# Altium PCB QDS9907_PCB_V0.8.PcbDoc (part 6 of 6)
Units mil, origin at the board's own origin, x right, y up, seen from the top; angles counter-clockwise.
Board outline 3410.03 x 4010.03 mil, 8 copper layers (Top Layer, GND1, INT1, INT2, PWR1, GND2, GND3, Bottom Layer), stack 81.668 mil thick; 250 components, 129 nets, 7010 pads, 701 vias.
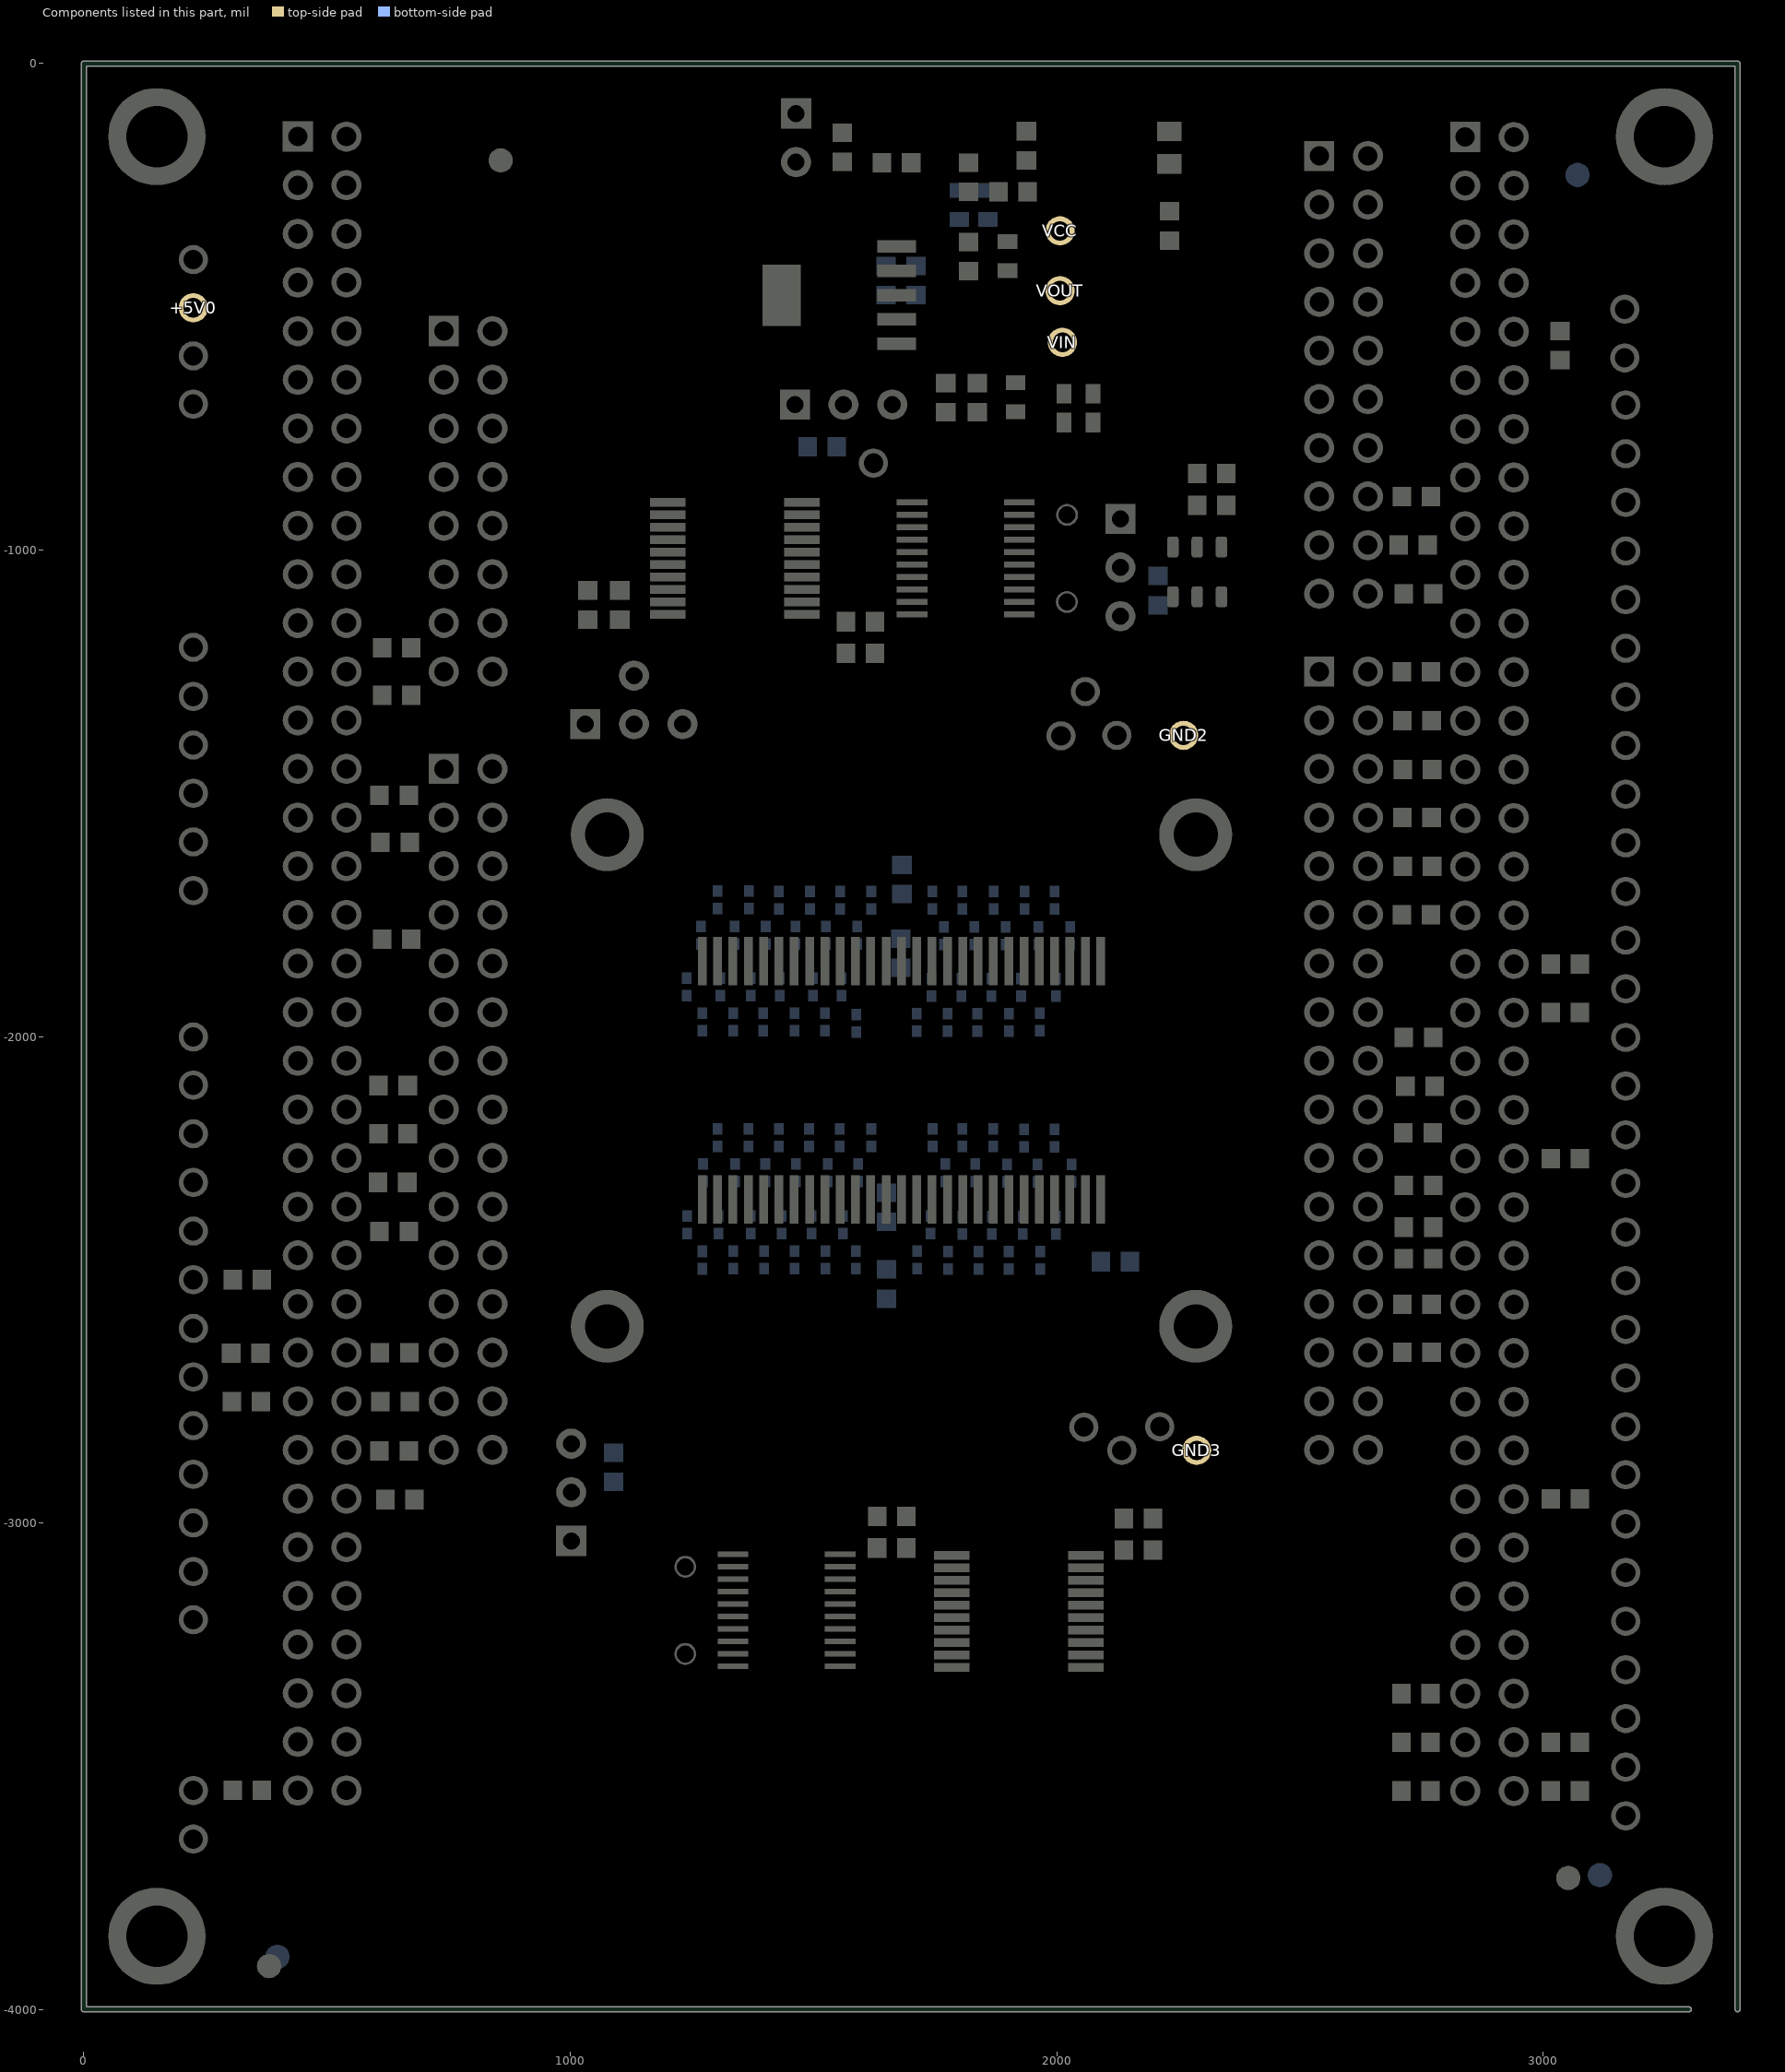
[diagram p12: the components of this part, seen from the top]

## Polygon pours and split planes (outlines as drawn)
+5V0 on PWR1 "+5V" (solid, remove dead copper, pour order 22): -8.31,-1058 1104,-1058 1247,-915 2003,-915 2003,-591.74 1748,-591.74 1748,-2 -6.17,-2
VCC on PWR1 "VCC" (solid, remove dead copper, pour order 21): 9,-1064 1112,-1064 1250,-926 2010,-926 2010,-592.67 1757,-592.67 1757,0 3404,0 3404,-3994.98 9,-3994.98
+5V0 on Top Layer "Top Layer-No Net" (solid, remove dead copper, pour order 23): 608,-798 606,-800 606,-973 636,-1003 999,-1003 1056,-946 1056,-865 1019,-828 990,-798
VOUT on Top Layer "Top Layer-No Net" (solid, remove dead copper, pour order 24): 1735,-424 1735,-411 1742,-404 1744,-402 1753,-402 2105,-402 2118,-415 2128,-425 2128,-454 2128,-481 2114,-495 2094,-515 2063,-515 1990,-515 1968,-493 1962,-487 1845,-487 1814,-487 1780,-453 1778,-451 1760,-451 1746,-451 1739,-444 1735,-440 1735,-424
GND on Top Layer "GND" (solid, remove dead copper, pour order 47): 0,-4000 0,0 3399,0 3399,-4000
VOUT on Bottom Layer "Top Layer-No Net" (solid, remove dead copper, pour order 25): 1788,-386.13 1950.13,-386.13 1954,-390 1962,-398 1965,-398 2118,-398 2131,-411 2145,-425 2145,-443 2145,-493 2128,-510 2122,-516 2077,-516 1979,-516 1961,-498 1953,-490 1935,-490 1837,-490 1788,-441 1788,-386.13
VIN on Bottom Layer "Top Layer-No Net" (solid, remove dead copper, pour order 26): 1726,-512 1944,-512 1956,-524 1970,-538 1985,-538 2049,-538 2065,-554 2072,-561 2072,-577 2072,-594 2057,-609 2042,-624 2017,-624 1756,-624 1728,-596 1718,-586 1718,-555 1718,-521 1726,-513
GND on Bottom Layer "GND" (solid, remove dead copper, pour order 45): 0,-4000 0,0 3399,0 3399,-4000
GND on GND1 "Top Layer-GND" (solid, remove dead copper, pour order 39): 0,-4002.85 0,0 3400,0 3400,-4005.02 0,-4005.01
GND on GND2 "Top Layer-GND" (solid, remove dead copper, pour order 41): 2,-3992 0,0 3400,0 3398,-3992 0,-3992
GND on GND3 "Top Layer-GND" (solid, remove dead copper, pour order 43): 3,-3999 0,-1.08 3400,0 3400,-3999 0,-3999
GND on INT1 "GND" (solid, remove dead copper, pour order 51): 0,-4000 0,0 3399,0 3399,-4000
GND on INT2 "GND" (solid, remove dead copper, pour order 49): 0,-4000 0,0 3399,0 3399,-4000

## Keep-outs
Keep-Out Layer:
  lines w25: 0,-4000 0,0 3399,0 3399,-4000 0,-4000

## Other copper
Top Layer:
  rectangle net GND: 2178,-3077 2263,-2965
  rectangle net GND: 1696,-3037 1785,-2961
  rectangle net GND: 1671.11,-3073 1720,-2961
  rectangle net GND: 1509.5,-1239.5 1566.5,-1168.5
  rectangle net GND: 1545.5,-1239.5 1587.5,-1122.5
  rectangle net +5V0: 1870,-770 1965,-698
  rectangle net +5V0: 1963,-770 2033,-645
  rectangle net NetR14_1: 1630,-390 1849,-331
  rectangle net GND: 1340.55,-636 1516,-325
  rectangle net VIN: 1742,-678 1948,-510
  rectangle net VIN: 1630,-550 1750,-510
  rectangle net VCC: 1865,-390 2103,-300
  rectangle net VOUT: 1740.99,-437 1789,-405.01
  pour cut-out: 2224,-1009 2350,-1007 2353,-1075 2220,-1075 2220,-1014
  pour cut-out: 3178,-3221 3192,-3274 3153,-3285 3158,-3227
  pour cut-out: 3199,-811 3199,-896 3177,-869 3181,-790
  pour cut-out: 3197,-1105 3195,-1599 3119,-1534 3169,-1116
  pour cut-out: 3025,-2272 3005,-2324 2984,-2293 2982,-2280
  pour cut-out: 3194,-3421 3192,-3487 3154,-3477 3157,-3423
  pour cut-out: 2680,-3451 2679,-3521.74 2720,-3521 2734,-3481
  pour cut-out: 3194,-2328.5 3200,-2377.5 3171,-2367.5 3156,-2328.5 3159,-2326.5
  pour cut-out: 3191,-3323 3192,-3387 3164,-3377 3167,-3336
  pour cut-out: 3192,-2423 3192,-2490 3173,-2479 3169,-2426
  pour cut-out: 3202,-2221 3192,-2287 3182,-2280 3171,-2231
  pour cut-out: 2613,-1243 2623,-1776 2675,-1770 2652,-1259
  pour cut-out: 2751,-866 2815,-825 2899.54,-829.1 2940,-851 2931,-923.8 2907,-934
  pour cut-out: 2619,-888 2633,-1255 2691,-1252 2673,-890
  pour cut-out: 2862.5,-996.5 2847.5,-1107.5 2772.5,-1084.5 2795.5,-1006.5 2800.5,-996.5
  pour cut-out: 2001.21,-942.91 2091.21,-894.91 2092.21,-963.91 2065.79,-1000.26 2022.21,-1007.74
  pour cut-out: 1967.5,-2964 2098.5,-2994 2011.5,-3052 1963.5,-3056 1907.5,-3036
  pour cut-out: 1811,-3275 1809,-3322 1741,-3322 1733,-3307 1745,-3289
  pour cut-out: 200,-2800 198,-2886 225,-2900 239,-2837 239,-2813
  pour cut-out: 200,-2605 199,-2778 235,-2771 239,-2634
  pour cut-out: 210,-2516 203,-2585 225,-2600 251,-2526
  pour cut-out: 453,-1683 547,-1671 550,-1632 501,-1609
  pour cut-out: 452,-1737 530,-1733 552,-1788 511,-1825 456,-1809
  pour cut-out: 703,-1635 694.34,-1755.69 906,-1747 932,-1717 861,-1630 778,-1606
  pour cut-out: 765,-1409 841.9,-1404.03 820,-1446 812,-1462
  pour cut-out: 872,-1464 882.86,-1633.28 844,-1640 823,-1549 847,-1481
  pour cut-out: 2122,-487 2191,-534 2163,-554 2096,-504
  pour cut-out: 2081,-593 2038,-667 2031.52,-613.55 2039.69,-608.48
  pour cut-out: 1867.87,-405.13 1847.18,-405.13 1845.04,-403 1848.73,-399.31 1848.73,-387.96 1859.96,-387.96 1867.87,-395.87
  pour cut-out: 1779.87,-425.13 1759.18,-425.13 1757.04,-423 1760.73,-419.31 1760.73,-407.96 1771.96,-407.96 1779.87,-415.87
  pour cut-out: 1482.16,-3270 1664,-3270 1664,-3326 1463,-3326 1463,-3268.08
  pour cut-out: 1409.15,-3192.95 1502.6,-3286.4 1463,-3326 1363.89,-3226.89 1404.2,-3186.59 1402.78,-3185.17
  pour cut-out: 1403,-3229 1535.16,-3229 1535.16,-3285 1395,-3285 1395,-3228 1393,-3228
  pour cut-out: 2036,-3228 2036,-3360.16 1980,-3360.16 1980,-3220 2037,-3220 2037,-3218
  pour cut-out: 1978.05,-3226.92 1845.89,-3226.92 1845.89,-3170.92 1986.05,-3170.92 1986.05,-3227.92 1988.05,-3227.92
  pour cut-out: 1690,-3346 1690,-3213.84 1746,-3213.84 1746,-3354 1689,-3354 1689,-3356
  pour cut-out: 1608.84,-3073 1741,-3073 1741,-3129 1600.84,-3129 1600.84,-3072 1598.84,-3072
  pour cut-out: 2170,-1107.08 2170,-974.92 2226,-974.92 2226,-1115.08 2169,-1115.08 2169,-1117.08
  pour cut-out: 1512.5,-918.5 1512.5,-877.5 1531.5,-877.5 1531.5,-926.5 1508.5,-926.5 1508.5,-918.5
  pour cut-out: 1451.5,-880.18 1451.5,-948.5 1320.5,-948.5 1320.5,-873.5
  pour cut-out: 183.34,-1590 257,-1590 257,-1511 183.34,-1511
  pour cut-out: 2827,-2000 2827,-2095 2827,-1813 2960,-1813 2960,-2082 2826,-2082 2826,-2084
  pour cut-out: 1982.87,-522.13 1962.18,-522.13 1960.04,-520 1963.73,-516.31 1963.73,-504.96 1974.96,-504.96 1982.87,-512.87
  pour cut-out: 1787.72,-474.99 1787.72,-501.72 1795,-509 1806.91,-497.09 1814,-497.09 1814,-490.6 1796,-472.6 1793.61,-474.99
  pour cut-out: 2739,-2032 2739,-1972.23 2738.77,-1972 2749,-1972 2749,-2032
  pour cut-out: 646,-2721 646,-2780.77 646.23,-2781 636,-2781 636,-2721
  pour cut-out: 631,-2134.89 631,-2075.12 630.77,-2074.89 641,-2074.89 641,-2134.89
  pour cut-out: 645,-2620 645,-2679.77 645.23,-2680 635,-2680 635,-2620
  pour cut-out: 634,-2882 634,-2822.23 633.77,-2822 644,-2822 644,-2882
  pour cut-out: 633,-1534 633,-1474.23 632.77,-1474 643,-1474 643,-1534
  pour cut-out: 639,-1831 639,-1771.23 638.77,-1771 649,-1771 649,-1831
  pour cut-out: 1621.74,-448.93 1618,-445.19 1618,-328.74 1625.82,-320.91 1731.96,-320.91 1737,-325.96 1729.66,-333.3 1729.66,-448.93
  pour cut-out: 1844,-179 1844,-239 1855,-239 1855,-249 1794,-249 1794,-229 1616,-229 1616,-179
  pour cut-out: 1794,-249 1794,-331 1965,-331 1965,-178 1915,-178 1915,-239 1855,-239 1855,-249
  pour cut-out: 2207,-329 2257,-329 2257,-339 2207,-339
  pour cut-out: 1985,-698 1861,-698 1861,-675 1965,-675 1965,-685 1970,-685
  pour cut-out: 640,-1329 640,-1269.23 639.77,-1269 650,-1269 650,-1329
  pour cut-out: 341,-2471 341,-2530.77 341.23,-2531 331,-2531 331,-2471
  pour cut-out: 2744,-3581 2744,-3521.23 2744.23,-3521 2734,-3521 2734,-3581
  pour cut-out: 2744,-3481 2744,-3421.23 2744.23,-3421 2734,-3421 2734,-3481
  region net VCC: 1237.5,-1123.5 1147.81,-1123.5 1016.5,-1123.5 1016.5,-1187.5 1237.5,-1187.5
  region net VCC: 1737.5,-1126 1657,-1126 1607.5,-1126 1607.5,-1240.5 1693.5,-1240.5 1737.5,-1196.5
  region net VCC: 2023,-3076 2112.69,-3076 2163,-3076 2163,-2970 2068,-2970 2023,-3015
  region net VCC: 1523,-3072 1602,-3072 1651,-3072 1651,-2966 1560,-2966 1523,-3003
  pour cut-out: 2728,-1780 2728,-1720.23 2727.77,-1720 2738,-1720 2738,-1780
  pour cut-out: 2728,-1680 2728,-1620.23 2727.77,-1620 2738,-1620 2738,-1680
  pour cut-out: 2728,-1580 2728,-1520.23 2727.77,-1520 2738,-1520 2738,-1580
  pour cut-out: 2728,-1480 2728,-1420.23 2727.77,-1420 2738,-1420 2738,-1480
  pour cut-out: 2728,-1380 2728,-1320.23 2727.77,-1320 2738,-1320 2738,-1380
  pour cut-out: 2728,-1280 2728,-1220.23 2727.77,-1220 2738,-1220 2738,-1280
  pour cut-out: 2728,-1120 2728,-1060.23 2727.77,-1060 2738,-1060 2738,-1120
  pour cut-out: 2728,-1020 2728,-960.23 2727.77,-960 2738,-960 2738,-1020
  pour cut-out: 2735,-920 2735,-860.23 2734.77,-860 2745,-860 2745,-920
  pour cut-out: 3065,-585 3005.23,-585 3005,-585.23 3005,-575 3065,-575
  pour cut-out: 3041,-1881 3041,-1821.23 3040.77,-1821 3051,-1821 3051,-1881
  pour cut-out: 3041,-1981 3041,-1921.23 3040.77,-1921 3051,-1921 3051,-1981
  pour cut-out: 3041,-2281 3041,-2221.23 3040.77,-2221 3051,-2221 3051,-2281
  pour cut-out: 3041,-2981 3041,-2921.23 3040.77,-2921 3051,-2921 3051,-2981
  pour cut-out: 3041,-3481 3041,-3421.23 3040.77,-3421 3051,-3421 3051,-3481
  pour cut-out: 3041,-3581 3041,-3521.23 3040.77,-3521 3051,-3521 3051,-3581
  pour cut-out: 2734,-3381 2734,-3321.23 2733.77,-3321 2744,-3321 2744,-3381
  pour cut-out: 2736,-2679 2736,-2619.23 2735.77,-2619 2746,-2619 2746,-2679
  pour cut-out: 2736,-2579 2736,-2519.23 2735.77,-2519 2746,-2519 2746,-2579
  pour cut-out: 2739,-2487 2739,-2427.23 2738.77,-2427 2749,-2427 2749,-2487
  pour cut-out: 338,-2621 338,-2680.77 338.23,-2681 328,-2681 328,-2621
  pour cut-out: 339,-2721 339,-2780.77 339.23,-2781 329,-2781 329,-2721
  pour cut-out: 341,-3520 341,-3579.77 341.23,-3580 331,-3580 331,-3520
  pour cut-out: 635,-1631 635,-1571.23 634.77,-1571 645,-1571 645,-1631
  pour cut-out: 640,-1231 640,-1171.23 639.77,-1171 650,-1171 650,-1231
  pour cut-out: 655,-2923.12 655,-2982.89 655.23,-2983.12 645,-2983.12 645,-2923.12
  pour cut-out: 2738,-2336 2738,-2276.23 2737.77,-2276 2748,-2276 2748,-2336
  pour cut-out: 2790,-2623.67 2790,-1971 2859,-1971 2863,-1967 2873,-1977 2873,-2643 2844,-2672 2828.36,-2656.36 2799.26,-2656.36
  pour cut-out: 1424,-2090 1426,-2088 1476,-2088 1476,-2073 1456,-2053 1445,-2064 1433.03,-2064 1429.03,-2068
  pour cut-out: 2056,-2843.09 2118.61,-2888.04 2155,-2871 2156,-2833 2164,-2867 2201,-2828 2148.57,-2774.18 2068.56,-2765.02
  pour cut-out: 1830,-3034
  pour cut-out: 1834,-3048 1840,-2974 1857,-2975 1881,-3021
  pour cut-out: 1672,-3067 1672,-2934 1650,-2931 1653,-3081 1659,-3081
  pour cut-out: 3194.4,-3570.2 3189,-3504 3139,-3544 3164,-3596
  pour cut-out: 399,-2988 401,-2780 433,-2782 430,-2972 421,-2986.34
  pour cut-out: 591,-2922 590,-2644 572,-2663 557,-2971 597,-2957
  pour cut-out: 1015,-2904 1014,-2759 984,-2776.56 990,-2840
  pour cut-out: 550,-2069 724,-2062 748,-2563 619,-2579 545,-2457 561,-2066
  pour cut-out: 256,-2041 258,-2101 250,-2089 237,-2048
  pour cut-out: 396,-2092
  pour cut-out: 397,-2113 396,-1983 444,-2040 402,-2131
  pour cut-out: 691,-1401
  pour cut-out: 392,-1399
  pour cut-out: 399,-1395 399.26,-1655.36 557,-1653 584,-1629 617,-1442 560,-1403 421,-1393
  pour cut-out: 2323,-813 2323,-974.95 2244,-975 2241,-932 2260,-929 2260,-813
  pour cut-out: 1597.5,-1119.47 1597.5,-1263 1593,-1263 1593,-1110 1590,-1110
  pour cut-out: 1411,-1154.12 1435,-1154.12 1435,-1223 1411,-1223
  pour cut-out: 1316,-1238.12 1340,-1238.12 1340,-1307 1316,-1307
  pour cut-out: 1245.45,-1414.14 1269.45,-1414.14 1269.45,-1483.03 1245.45,-1483.03
  pour cut-out: 2063,-968 2175,-968 2175,-1044 2064,-1044 2064,-1014
  pour cut-out: 2792,-1780 2800.31,-1780 2800.31,-1737 2649,-1737 2649,-1780 2674,-1780
  pour cut-out: 2742,-2132 2742,-2072.23 2741.77,-2072 2752,-2072 2752,-2132
  pour cut-out: 2739,-2228 2739,-2168.23 2738.77,-2168 2749,-2168 2749,-2228
  pour cut-out: 2738,-2336 2738,-2276.23 2737.77,-2276 2748,-2276 2748,-2336
  pour cut-out: 2739,-2422 2739,-2362.23 2738.77,-2362 2749,-2362 2749,-2422
  pour cut-out: 3198.34,-1930.35 3196,-1930.35 3196,-1979 3161,-1979 3161,-1934
  pour cut-out: 865.01,-2051.86 865.01,-2533 903,-2533 903,-2566 828,-2566 828,-2569 784,-2569 784,-2042.38
  pour cut-out: 1256.38,-1349.19 1280.38,-1349.19 1280.38,-1418.08 1256.38,-1418.08
  pour cut-out: 985.45,-1357.14 1009.45,-1357.14 1009.45,-1426.03 985.45,-1426.03
  pour cut-out: 676,-1623 708,-1671 730,-1668 722,-1631
  pour cut-out: 460,-1860 514,-1861 500.31,-1839.37 463,-1841
  pour cut-out: 399.26,-1755.36 385,-1781 417,-1846 456,-1809 452,-1782
  pour cut-out: 568,-1748 604,-1773 613,-1841.5 560,-1850 540,-1780
  pour cut-out: 705,-1731 668,-1783 709,-1794 723.02,-1787.34
  pour cut-out: 393,-1198 418,-1168 467,-1167 577.96,-1165.72 611,-1187 535,-1219 420,-1240 395,-1205
  pour cut-out: 414,-1262 392,-1293 404.42,-1329.46 464,-1327 465,-1292
  pour cut-out: 597,-1316 598,-1395 565.01,-1382.6 572.6,-1324.99
  pour cut-out: 1407,-865 1386,-876.84 1394,-911 1475.81,-927.5 1512.5,-918.5 1529,-894 1512.5,-877.5 1479,-866
  pour cut-out: 2780,-1776 2824.28,-1788.96 2820,-1770 2802.04,-1766.72
  pour cut-out: 2638,-2378 2637,-2427 2658,-2424 2668,-2386 2653,-2378
  pour cut-out: 2691,-3368 2709,-3413 2744,-3406 2726,-3362
  pour cut-out: 868,-2155 920,-2195 912,-2214 843,-2192
  pour cut-out: 1230,-1189 1284.5,-1225.5 1294,-1181 1244,-1171
  pour cut-out: 1846,-871 1848,-937 1992,-931 1982,-873 1860,-863
  pour cut-out: 1660,-728 1640,-799 1622,-790 1632,-740
  pour cut-out: 3188,-1820 3187,-1894 3173,-1886 3168,-1823
  pour cut-out: 1275,-3210 1242,-3251 1285.32,-3269.23 1305,-3254
  pour cut-out: 666,-2590 658,-2635 719,-2663 824,-2668 912,-2699 873,-2587 742,-2581
  pour cut-out: 519.18,-2621.94 595,-2621 590,-2644 564,-2658
  pour cut-out: 376,-2498 436,-2534 499.26,-2555.36 595,-2621 546,-2673 376,-2622
  pour cut-out: 381,-2403 427,-2442 533,-2460 535,-2423 464,-2388
  pour cut-out: 1281,-1435 1270,-1500 1245.45,-1483.03 1253,-1446
  pour cut-out: 1296,-1308 1273,-1363 1246,-1349 1245.6,-1319.66
  pour cut-out: 1665,-3052 1682,-3082 1659,-3081
  pour cut-out: 2641,-2477 2638,-2633 2660,-2629 2654,-2459
  pour cut-out: 2703,-2219 2701,-2290 2717,-2289 2716,-2220
  pour cut-out: 3195,-2016 3194,-2090 3164.77,-2062.26 3169,-2003
  pour cut-out: 2856,-1756 2949,-1760 2987,-1702 2977.96,-1666.72 2903,-1674 2876,-1685
  pour cut-out: 2038,-1301 2012,-1357 2124,-1381 2078,-1307
  pour cut-out: 226,-3025 223,-3083 247,-3084 245.04,-3034.72
  pour cut-out: 1510,-3029 1476,-3031 1460,-3053 1474,-3080 1514,-3082 1537,-3044 1523,-3037.5
  pour cut-out: 1607,-887 1661.5,-886.28 1661.5,-908.61 1623,-920 1608,-919
  pour cut-out: 863,-1173 864,-1236 841,-1235 837,-1218 848,-1174
  pour cut-out: 1542,-904 1512.5,-918.5 1508.5,-926.5 1524,-950 1558,-947 1565,-933 1560,-913
  text "TOP" at 4116.71,-1832.72 h65
GND1:
  text "GND1" at 5473,-1976 h65
PWR1:
  text "PWR1: +5V0, VCC" at 4086,-2280 h75
INT1:
  pour cut-out: 1944,-2811 1933,-2780 1971,-2776 1957,-2810
  pour cut-out: 1858.17,-2763.49 1825.13,-2745 1833.23,-2727.64
  pour cut-out: 2197,-2400 2226,-2388 2193,-2376
  pour cut-out: 2465.88,-2409.12 2494,-2415 2457,-2418
  pour cut-out: 2508.12,-2393.12 2506,-2366 2521,-2371 2517,-2402
  pour cut-out: 2500.31,-2339.37 2479.12,-2311.88 2493,-2296 2523,-2340
  pour cut-out: 759,-3263 769,-3233 742,-3254
  pour cut-out: 896,-3270 933,-3263 898,-3252
  pour cut-out: 899,-3337 892,-3316 882,-3345
  pour cut-out: 406,-3302 395,-3247 393,-3201 433,-3239 413,-3307
  pour cut-out: 404.12,-3394.12 375,-3364 405,-3339 413,-3403
  pour cut-out: 348,-3095 392,-3091 387,-3131 352,-3132
  pour cut-out: 185.26,-2105.23 148,-2096 157,-2130 189.26,-2117.97
  pour cut-out: 250.04,-1487.79 279.3,-1468.56 252.3,-1462.56
  pour cut-out: 152,-1481 119,-1471 118,-1486
  pour cut-out: 154,-1909 190,-1897 151,-1889
  pour cut-out: 895,-2129 949,-2136 932,-2184 892,-2160 895,-2141
  pour cut-out: 973,-2023 1041.56,-2029.2 1022,-2065 967,-2072
  pour cut-out: 1254.56,-2207.54 1299,-2213 1282.26,-2173.73 1271,-2183
  pour cut-out: 621,-1928 679,-1937 670,-1988 623,-1987 623,-1969
  pour cut-out: 1431,-2130 1425,-2159 1410,-2151
  pour cut-out: 1323,-2159 1315.61,-2173.05 1301,-2149
  pour cut-out: 1361,-2344 1391,-2347 1390,-2328 1368,-2334
  pour cut-out: 1532.85,-2313.09 1550,-2305 1532,-2334 1523.97,-2321.97
  pour cut-out: 1739.56,-2148 1757,-2133 1735.88,-2139.12
  pour cut-out: 1843,-2075 1844,-2039 1818,-2048
  pour cut-out: 2036,-2168 2048,-2144 2021,-2157
  pour cut-out: 2158,-1989.56 2184,-2004 2186,-1983 2160.45,-1989.32
  pour cut-out: 2112,-1985 2104,-2012 2092.42,-1989.65
  pour cut-out: 2969.05,-2121.95 3045,-2124 3042,-2169 2953,-2169 2954,-2142
  pour cut-out: 3057,-3181 3081,-3186 3076,-3152 3061,-3163
  pour cut-out: 1419,-2812 1455,-2797 1447,-2833
  pour cut-out: 1374,-2881 1411,-2878 1399,-2822 1365,-2844
  pour cut-out: 1418,-2725 1482,-2718 1479,-2662 1435,-2662
  pour cut-out: 1551,-2720 1535,-2681 1501,-2723
  pour cut-out: 1412,-2634 1425,-2588 1369,-2573 1356,-2632 1398,-2662
  pour cut-out: 1717,-2573 1691,-2563 1726,-2546
  pour cut-out: 1636,-2545 1630.57,-2522.99 1626.89,-2531.87
  pour cut-out: 262.88,-2841.12 262.03,-2815.34 270,-2770 247,-2766 242,-2814 254,-2837.44
  pour cut-out: 1074,-2796 1085,-2764 1039,-2777 1046,-2788
  pour cut-out: 1039.96,-2921.28 1050,-2902 1014,-2892 1017,-2915
  pour cut-out: 1039.96,-2952.72 1041,-2985 1015,-2984
  pour cut-out: 964,-3492 998,-3534 962,-3540 939,-3523
  pour cut-out: 1626.49,-2876.48 1682,-2903 1676.12,-2866.12 1657,-2859
  pour cut-out: 1547,-2885 1595,-2896 1588,-2917 1536,-2909
  pour cut-out: 1636,-2811.56 1650,-2844 1668,-2829 1653,-2811
  pour cut-out: 1697,-2229 1655,-2234 1654,-2282 1678,-2292 1706,-2285
  pour cut-out: 1685,-2124 1643,-2140 1618.24,-2226 1681,-2252 1716.88,-2234.88 1740,-2176
  pour cut-out: 2519.46,-2114.42 2456,-2110 2440,-2132 2451,-2165 2504.42,-2170.54 2540,-2150
  pour cut-out: 2074,-1120 2131,-1136 2131,-1205 2078,-1207 2059,-1194
  pour cut-out: 1712,-786 1734,-776 1783,-812 1771,-831 1716,-819.5
  pour cut-out: 1320,-760 1360,-785 1352,-789 1312,-795
  pour cut-out: 626,-1464 719,-1546 709,-1814 767,-1811 783,-1468 682,-1420
  pour cut-out: 170,-1275 244,-1302 302,-1300 285,-1248 259.72,-1220.04 199,-1214 183,-1254
  pour cut-out: 242,-2120 249,-2185 219,-2182 219,-2127
  pour cut-out: 816,-2915 902,-2890 877.96,-2865.72 807,-2900
  pour cut-out: 1222,-2503 1305,-2508 1233.23,-2489.55 1223,-2494
  pour cut-out: 1315,-2530.56 1329,-2562 1342.58,-2530.65 1315,-2518
  pour cut-out: 1112.27,-2348.27 1079,-2363 1077,-2338
  pour cut-out: 1164,-2349 1145,-2378 1136.42,-2354.65 1136.45,-2354.56
  pour cut-out: 1110,-2286 1075,-2302 1089,-2322 1103.35,-2321.58
  pour cut-out: 1184,-2348 1154.5,-2363.5 1150,-2393 1188,-2407 1219,-2390 1218,-2368
  pour cut-out: 1152.25,-2378.25 1136,-2432 1187.5,-2436 1188,-2407
  pour cut-out: 1108,-2437 1132,-2479 1156,-2455 1153,-2436
  pour cut-out: 1138,-2488 1089,-2530 1123,-2581 1189,-2530 1138,-2500
  pour cut-out: 1274,-1802 1246,-1839 1240,-1904 1258.29,-1897.29 1298.44,-1854.2 1291.5,-1829.5
  pour cut-out: 1239,-1733 1271,-1772 1291,-1758 1287,-1744
  pour cut-out: 1256,-1696 1234,-1724 1293,-1735 1303,-1728 1277,-1700
  pour cut-out: 2023,-1821 1995,-1881 1965,-1855 1991,-1819
  pour cut-out: 2000,-1472 2079,-1483 2078,-1508 2028,-1517
  pour cut-out: 1904,-1462 1881,-1503 1865,-1488 1866.59,-1472.83
  pour cut-out: 1905,-1588 1922,-1629 1891.45,-1619.44 1877,-1624
  pour cut-out: 1793,-745 1743.94,-752 1749,-802 1766,-815 1793,-808 1802.44,-788.8 1805,-773
  pour cut-out: 3262,-2047 3221.5,-2077.5 3249,-2111 3261,-2112
  pour cut-out: 3146,-2006 3120,-2053 3178,-2071 3207,-2066 3212,-2055 3186,-2004
  pour cut-out: 3173,-2518 3243,-2549 3244,-2513 3218,-2508
  pour cut-out: 2759,-3202 2726.5,-3253.5 2710,-3228 2716.12,-3211.88
  pour cut-out: 1355,-3477 1356,-3540 1427,-3555 1397,-3482
  pour cut-out: 678,-3125 624,-3150 630,-3180 672,-3193
  pour cut-out: 250,-3146 288,-3215 311,-3190 284,-3130
  pour cut-out: 193,-3005 173,-3142 234,-3125 244,-3050
  pour cut-out: 646,-1291 676,-1387 720,-1386 732,-1288
  pour cut-out: 2440,-1040 2399,-1069 2436,-1101 2446,-1089
  pour cut-out: 1765,-898 1773,-971 1732.26,-942.97 1739.11,-920.29
  pour cut-out: 1763.5,-845.5 1765,-898 1730.53,-896.24 1727,-874
  pour cut-out: 1792,-644 1747,-675 1746,-651 1763,-633
  pour cut-out: 667,-3268 630,-3289 619,-3265 627,-3252
  pour cut-out: 762,-3375 747,-3419 800,-3415 803,-3395
  pour cut-out: 747,-3419 723,-3458 704,-3445 698,-3424
  pour cut-out: 1264,-3203 1242,-3251 1294,-3259 1303.41,-3231.46
  pour cut-out: 1388.77,-3269.23 1432,-3298 1439,-3256 1425,-3232
  pour cut-out: 1451,-3334 1560,-3330 1556,-3311 1454,-3325.51
  pour cut-out: 2148,-1392 2172,-1432 2116,-1457 2107,-1402
  pour cut-out: 2350,-1415 2369,-1451 2334,-1452 2330,-1447
  pour cut-out: 1633,-1387 1608,-1422 1596,-1410
  pour cut-out: 1688,-1442.5 1651,-1466 1667,-1500 1679,-1499
  pour cut-out: 2779,-632 2825,-660 2926,-656 2965,-653 3020,-628 2995,-601 2926,-601 2810,-601 2790.5,-620.5
  pour cut-out: 2992.5,-640.5 3099,-641 3087,-618 3025,-614 2983,-620
  pour cut-out: 223,-1521 225,-1727.5 225,-1755 139,-1761 156,-1561 178,-1521
  pour cut-out: 418,-1765 390,-1800 414,-1843 607,-1827 565,-1759 451,-1753
  pour cut-out: 380,-1903 396,-2009 466,-1994 461,-1885 420,-1852 386,-1895
  pour cut-out: 1288,-1074 1249,-1095 1227.3,-1107.06 1221,-1147 1289,-1155 1315,-1131 1302,-1101
  text "INTERNAL 1" at 4097.54,-1970.95 h65
INT2:
  pour cut-out: 1532,-1568 1618,-1568 1632,-1582 1629,-1585 1629,-1608 1606,-1608 1582,-1632 1554,-1604 1534,-1604 1534,-1579 1528,-1573
  pour cut-out: 2480,-1180 2440,-1190 2441,-1174
  pour cut-out: 2474,-1622 2438,-1601 2441,-1647 2448.66,-1638.7
  pour cut-out: 1109,-1788 1150,-1790 1147,-1757 1114,-1769
  pour cut-out: 1985.52,-2162.06 1912,-2168 1914,-2186 1966,-2189 1983,-2182
  pour cut-out: 2486,-2517 2509,-2498 2473,-2491 2474,-2502
  pour cut-out: 2455,-2604 2489,-2587 2448,-2589 2451,-2611
  pour cut-out: 2655,-2580
  pour cut-out: 1950.19,-1213.61 1906.35,-1236.42 1918,-1178 1944,-1193
  pour cut-out: 2007,-1659 1995,-1638 1981,-1659
  pour cut-out: 1969.32,-1154.64 1933,-1163 1937,-1133 1961,-1129
  pour cut-out: 3044,-1043 3072,-1019 3040,-996 3037,-1030
  pour cut-out: 974,-2022 1029,-2026 1027,-2067 981,-2089 978,-2045
  pour cut-out: 799.88,-1907.88 887,-1920 866,-1998 799.32,-1994.55 798,-1957
  pour cut-out: 1814,-2768 1865.44,-2774.2 1853,-2811 1816,-2807 1815,-2774
  pour cut-out: 1885,-2853 1903,-2846 1902,-2843 1887,-2830 1885,-2852
  pour cut-out: 1912,-2773 1954,-2762 1919,-2746 1911,-2770
  pour cut-out: 1388,-2919 1419,-2907 1401,-2932 1389,-2924
  pour cut-out: 879.97,-2163.25 880.74,-2855.36 808,-2850 814.99,-2582.6 846,-2143
  pour cut-out: 834.64,-2890.74
  pour cut-out: 829,-2883 819,-2921 796,-2901 831,-2875
  pour cut-out: 872,-2194 896,-2185 880.08,-2180.84
  pour cut-out: 1001,-2359 1023,-2346 1002,-2343
  pour cut-out: 1395,-2510 1369.98,-2500.29 1404,-2480 1400,-2509
  pour cut-out: 1362,-2465 1368,-2432 1380,-2422
  pour cut-out: 1313,-2432 1368,-2432 1344,-2403 1324.75,-2424.65
  pour cut-out: 1345.24,-2384.43 1356,-2365 1353.25,-2391.28
  pour cut-out: 1458,-2313 1437,-2298 1435,-2322 1460.98,-2322.02
  pour cut-out: 1665,-2503 1649.55,-2483 1646.72,-2500.18
  pour cut-out: 924,-2195 952,-2184 931,-2214
  pour cut-out: 3212.77,-2794.25 3207.6,-2609.01 3159.62,-2640.72 3169,-2793
  pour cut-out: 2988,-2878 2956,-2868 2902.04,-2866.72 2812,-2868 2801,-2904 2800.31,-2940.37 2814,-3004
  pour cut-out: 2791,-3153
  pour cut-out: 2768.28,-3132.83 2784,-3137 2774,-3188 2728,-3181 2726.64,-3157.82
  pour cut-out: 2747,-2932 2789,-2929 2785,-2977 2742,-2972
  pour cut-out: 2305,-3141.43 2305,-3187 2281,-3179
  pour cut-out: 1557,-1249 1598,-1230 1601,-1246.5 1566,-1267
  pour cut-out: 1590,-878 1604,-921 1627.47,-904.53 1614,-876
  pour cut-out: 1629,-948 1655,-994 1629.42,-994.33 1610,-972
  pour cut-out: 1752.37,-953.21 1807.6,-934.38 1808,-972 1773.15,-978.96
  pour cut-out: 2047,-1136 2062,-1199 2021,-1198 2011.75,-1151
  pour cut-out: 1751,-873
  pour cut-out: 1815,-873 1814.21,-927.78 1772.48,-891.78 1789,-869
  pour cut-out: 1834,-1567 1870,-1614 1834,-1640 1812,-1617
  pour cut-out: 1914,-1499 1859,-1510 1875.32,-1476.55 1885,-1469
  pour cut-out: 1919,-1396 1877,-1427 1900,-1437 1919,-1424 1925,-1409
  pour cut-out: 1875,-1244 1916,-1277 1912,-1227
  pour cut-out: 1676,-1290 1723,-1311 1728,-1281 1712.41,-1271.35
  pour cut-out: 2072,-1505 2118,-1524 2106,-1544 2064,-1531
  pour cut-out: 2696,-1042 2697,-1162 2624,-1166 2648,-1038
  pour cut-out: 2418,-1955 2440,-1996 2394,-1998 2390,-1984
  pour cut-out: 2192,-2082 2228,-2128 2243,-2109 2245,-2091
  pour cut-out: 957,-2677 864,-2716 861,-2690 887,-2668
  pour cut-out: 974,-2548 1046,-2587 1084,-2653 1040,-2735 959,-2652
  pour cut-out: 1129,-2489 1091,-2530 1134,-2584 1165,-2543
  pour cut-out: 1012.5,-2403.5 975,-2424 972,-2404 984.56,-2393.35
  pour cut-out: 690,-2000 716,-2042 733,-2032 729.37,-1989.69
  pour cut-out: 1572,-3108 1514,-3143 1516,-3098 1551,-3062
  pour cut-out: 3046,-2861 3012,-2868 3012,-2917 3047,-2934 3069,-2917 3072,-2889
  pour cut-out: 1652,-2235 1644,-2321 1607,-2305 1604.74,-2244.2 1611.03,-2240.99
  pour cut-out: 1189,-2139 1301,-2141 1295,-2164 1187,-2169
  pour cut-out: 882,-1977 958,-1981 962,-1950 931,-1942 877,-1946
  pour cut-out: 1463,-1633 1527,-1668 1531,-1615 1498,-1601
  pour cut-out: 1523.52,-1915.54 1578,-1923 1581,-1904 1550,-1897
  pour cut-out: 1719,-1922 1767,-1917 1743,-1906 1712,-1907
  pour cut-out: 1881,-2076 1892,-2164 1863,-2166 1850,-2132 1852,-2083
  pour cut-out: 1669,-2433 1757,-2471 1779.88,-2502.12 1733.92,-2498.44 1680,-2474
  pour cut-out: 1649,-2754 1624,-2797 1614.19,-2766.6 1619,-2755
  pour cut-out: 1511.5,-2832 1595,-2914 1571,-2933 1468,-2874
  pour cut-out: 1216,-2352 1214,-2422 1244,-2422 1232,-2358
  pour cut-out: 1234,-2725 1219,-2776 1258,-2777 1264,-2755
  pour cut-out: 1129,-2775 1112,-2813 1083,-2803 1081,-2790
  pour cut-out: 2557,-2648 2554,-2850 2585,-2884 2619.46,-2885.58 2638,-2835 2637,-2628 2601.88,-2609.12 2564,-2620
  pour cut-out: 2662,-2547 2698,-2565 2703,-2550 2677.96,-2534.28
  pour cut-out: 2594.5,-2501 2616,-2542 2633,-2542 2642,-2513
  pour cut-out: 2547,-2272 2545,-2322 2534,-2322 2519.46,-2285.58
  pour cut-out: 2540,-2350 2663,-2354 2679,-2408 2562,-2426 2550,-2398
  pour cut-out: 2456,-2352 2408,-2397 2448,-2423 2467,-2420
  pour cut-out: 3190,-1819 3193,-1885 3168,-1890 3170,-1861.92
  pour cut-out: 1429,-1249 1358,-1288 1362,-1263 1384,-1247
  pour cut-out: 1206,-1258 1210,-1306 1179,-1303 1179,-1284
  pour cut-out: 1278,-2283 1248,-2346 1282,-2350 1330,-2325 1324,-2308
  pour cut-out: 1306,-2511 1407,-2525.5 1402,-2494.5 1323,-2479
  pour cut-out: 2757,-1671 2834,-1731 2925,-1741 2973,-1754 3047,-1780 3010,-1800 3010,-1907 2788,-1900 2758,-1698
  text "INTERNAL 2" at 4091,-2114 h65
GND2:
  text "GND2" at 5453,-2120 h65
Bottom Layer:
  rectangle net GND: 1611,-2340 1722,-2286
  rectangle net VCC: 1619,-2501 1682,-2361
  rectangle net GND: 1655,-1893 1728,-1839
  rectangle net VCC: 1648,-1821 1712,-1688
  rectangle net VCC: 1249.95,-1718 1642.95,-1678
  region net VCC: 2048.95,-1675 1720.95,-1675 1720.95,-1715 2048.95,-1715
  region net VCC: 2019.45,-2461 1694.45,-2461 1694.45,-2501 2019.45,-2501
  rectangle net VCC: 1221.45,-2501 1611.45,-2461
  rectangle net VCC: 1687,-2016 2026,-1976
  rectangle net VCC: 1213,-2015 1616,-1975
  rectangle net GND: 1717,-2382 2144.53,-2286
  rectangle net GND: 1191,-2386 1611,-2285
  rectangle net GND: 1718,-1893 2144,-1798
  rectangle net GND: 1188,-1893 1611,-1798
  rectangle net VOUT: 1613,-441 1788,-386.13
  rectangle net +5V0: 1868,-770 1992,-646
  rectangle net GND: 1433,-149.11 1496,-102.65
  rectangle net GND: 1743,-278 1900.99,-221
  rectangle net VCC: 1761,-375 2108,-296
  rectangle net NetJP12_2: 1433,-202.65 1496,-157
  rectangle net VCC: 1244,-2206 1647,-2166
  region net VCC: 2120,-2166 1717,-2166 1717,-2206 2120,-2206
  pour cut-out: 1802,-461 1768,-525 1830,-512 1833,-513
  pour cut-out: 2147.33,-511.9 2083.19,-584 2072,-561 2075,-515
  pour cut-out: 1505.74,-143.65 1423.35,-143.65 1423.35,-158.91 1505.74,-158.91
  pour cut-out: 1642.95,-1667.91
  pour cut-out: 1642.95,-1667.91 1642.95,-1675 1718.34,-1675 1718.34,-1667.91
  pour cut-out: 1220.45,-2377 1615,-2377 1615,-2427 1220.45,-2427
  pour cut-out: 1592,-2511 1707,-2511 1707,-2498 1592,-2498
  pour cut-out: 1688,-2408 2018.45,-2408 2018.45,-2378 1688,-2378
  pour cut-out: 1253,-2279 1633.97,-2279 1633.97,-2288 1253,-2288
  pour cut-out: 1692,-2280 2072.97,-2280 2072.97,-2289 1692,-2289
  pour cut-out: 1676,-1982 1676,-1886 2019,-1886 2019,-1930 1725,-1930 1725,-1973.39 1677.26,-1973.39
  pour cut-out: 1608.8,-1938 1608.8,-1887 1218,-1887 1218,-1938
  pour cut-out: 1248.95,-1796 1248.95,-1803 1642,-1803 1642,-1785.14 1249,-1785.14 1249,-1787
  pour cut-out: 1718,-1806 2047.95,-1806 2047.95,-1787 1718,-1787
  pour cut-out: 1059,-2900 1120,-2900 1120,-2877 1059,-2877
  pour cut-out: 904,-2215 904,-2225 914.12,-2226.12 927,-2219 905,-2215
  pour cut-out: 1523,-1127 1499,-1115 1496.88,-1129.88 1509,-1135
  pour cut-out: 1677,-1124 1678.75,-1138.39 1684,-1151 1705,-1156 1722,-1180 1708.79,-1198.03 1668,-1199 1655.23,-1176.76 1637,-1143 1667.88,-1135.89
  pour cut-out: 1095.42,-1237.46 1079,-1211 1103,-1215 1102,-1237
  pour cut-out: 1163.6,-1232.99 1181,-1215 1145,-1204 1143,-1229
  pour cut-out: 3196.8,-3542.44 3194.11,-3525.23 3167.15,-3519.53 3146,-3519 3137,-3546 3146.69,-3552.46
  pour cut-out: 3204.72,-3581.96 3208.98,-3565.44 3166,-3550 3129,-3556 3129,-3566 3138.2,-3577.6 3174,-3583
  pour cut-out: 2056,-3068 2063,-3050 2091,-3054 2121.3,-3033.25 2105.76,-3007.5 2107,-2984 2060,-2985 2044,-3037 2055,-3067
  pour cut-out: 1746,-3327 1774,-3304 1735,-3299 1736,-3318
  pour cut-out: 2208,-3324 2248,-3329 2257,-3369 2227,-3380 2205,-3357
  pour cut-out: 891,-2713 923,-2713 923,-2696.45 893,-2696.45 893,-2707
  pour cut-out: 906,-2127 950,-2127 950,-2174 907,-2174 907,-2159
  pour cut-out: 2155.09,-493 2155.09,-525.18 2079.13,-601.13 2068.5,-590.5 2068.5,-527.69 2103.19,-493
  pour cut-out: 2002,-653 2002,-616.55 1998.45,-613 1997.45,-614 1859,-614 1857.91,-615.09 1857.91,-646 1872,-646 1883,-657
  pour cut-out: 2238.5,-1078.5 2178.73,-1078.5 2178.5,-1078.27 2178.5,-1088.5 2238.5,-1088.5
  pour cut-out: 1513,-758 1513,-817.77 1512.77,-818 1523,-818 1523,-758
  pour cut-out: 2118,-406 2118,-346.23 2118.23,-346 2108,-346 2108,-406
  pour cut-out: 2434,-3672 2435,-3673 2435,-3701 2426,-3701 2419.81,-3694.81 2419.81,-3689.6
  pour cut-out: 2116,-3631 2134,-3671 2130,-3674 2099.32,-3665.35 2098,-3648
  pour cut-out: 1802.5,-3661.5 1783,-3700 1828,-3699 1832,-3689
  pour cut-out: 1730,-3458 1786,-3484.5 1791,-3458 1739,-3439
  pour cut-out: 2087,-3236 2068,-3286 2046,-3276 2046.25,-3250.48
  pour cut-out: 2436,-3205 2427,-3240 2416,-3238 2416,-3225.44 2413,-3211
  pour cut-out: 2222,-3008 2201,-3043 2194,-3028 2198,-3019
  pour cut-out: 2302,-3143 2327,-3195 2286,-3199 2278,-3185 2278,-3166
  pour cut-out: 972.95,-2866.05 966.42,-2916.46 998,-2918 996,-2860
  pour cut-out: 2970,-2039 3018,-2050 3054,-2057 3059,-2086 3062,-2097 2989,-2091 2958,-2068
  pour cut-out: 3066,-2028 3109,-2052 3093,-2072 3056.5,-2071.5
  pour cut-out: 3198,-817 3198,-879 3183,-878 3175,-838
  pour cut-out: 2268,-3092 2291.5,-3140.5 2311,-3106.43 2305,-3097
  pour cut-out: 2728,-2950 2761,-2994 2725,-3008 2707,-2985
  text "BOTTOM" at 5474.54,-1832.95 h65

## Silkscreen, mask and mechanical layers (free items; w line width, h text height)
Top Overlay:
  drawing of 3548 lines, arcs and shapes, not listed
  text "1" at 2818,-59 h34
  text "2" at 2941,-69 h34
  text "1" at 1372,-116 h35
  text "1" at 2511,-125 h34
  text "2" at 2648,-126 h34
  text "1" at 344,-162 h40
  text "2" at 630,-169.65 h40
  text "GND" at 80,-420 h35
  text "1" at 728,-465 h40
  text "2" at 830,-467 h40
  text "D13_2" at 2978,-498.67 h25
  text "D13_2" at 2809,-512.67 h25
  text "GND" at 3232,-523 h35
  text "VCC" at 3239,-625 h35
  text "IOREF" at 607,-693 h25
  text "RST" at 78,-718 h35
  text "R\S\T\" at 585,-784.43 h25
  text "D0_2" at 2530,-850.67 h25
  text "D15" at 1978,-879 h35
  text "+5V0" at 765,-912 h25
  text "D1_2" at 2531,-1051.67 h25
  text "A6_1" at 2535,-1155.67 h25
  text "A12_1" at 885,-1176.67 h25
  text "D8" at 1993,-1188 h35
  text "A7_1" at 2534,-1206.67 h25
  text "A13_1" at 890,-1263.67 h25
  text "1" at 940,-1375 h25
  text "D6_2" at 2524,-1412.67 h25
  text "CEB_1" at 889,-1448.67 h25
  text "MRAM" at 3235,-1480 h30
  text "MRAM" at 53,-1487 h30
  text "D8_2" at 2524,-1511.67 h25
  text "CEb" at 53,-1531 h30
  text "OEb_ALT" at 3212,-1532 h30
  text "MRAM" at 46,-1593 h30
  text "A8_1" at 2526,-1610.67 h25
  text "WEB_1" at 713,-1612.67 h25
  text "WEb" at 46,-1637 h30
  text "D10_2" at 2506,-1710.67 h25
  text "MRAM" at 57,-1718 h30
  text "OEb" at 54,-1767 h30
  text "OEB_1" at 714,-1810.67 h25
  text "A9_1" at 2532,-1811.67 h25
  text "A5_1" at 2834,-1813.67 h25
  text "A4_1" at 2834,-1912.67 h25
  text "DFFB" at 618,-1935 h25
  text "D5_2" at 2529,-2011.67 h25
  text "A20_1" at 715,-2110.67 h25
  text "A18_1" at 2415,-2111.67 h25
  text "A21_1" at 711,-2210.67 h25
  text "A17_1" at 2413,-2211.67 h25
  text "A16_1" at 2411,-2313.67 h25
  text "D4_2" at 2966,-2322.67 h25
  text "MRAM" at 49,-2390 h30
  text "A19_1" at 852,-2406.67 h25
  text "D7_2" at 2528,-2415.67 h25
  text "SEb" at 49,-2434 h30
  text "D9_2" at 2523,-2512.67 h25
  text "SEB_1" at 900.33,-2514 h25 r270
  text "D2_2" at 676.33,-2524 h25 r270
  text "A2_1" at 582.33,-2529 h25 r270
  text "TOP SILKSCREEN" at 4089.96,-2575.94 h65
  text "A1_1" at 349,-2599.67 h25
  text "D11_2" at 2507,-2609.67 h25
  text "D3_2" at 871,-2701.67 h25
  text "D12_2" at 2509,-2710.67 h25
  text "SHDN" at 895,-2759 h25
  text "A10_1" at 841,-2813.67 h25
  text "A0_1" at 452,-2814.67 h25
  text "1" at 1123.19,-2842 h50
  text "A3_1" at 2838,-2910.67 h25
  text "GND" at 3235,-2916.2 h35
  text "1" at 1081,-3057 h40
  text "OE" at 3239,-3094 h30
  text "BUFb" at 3239,-3138 h30
  text "D0" at 1136,-3139 h35
  text "BUFB" at 2992,-3165 h25
  text "GND" at 79,-3219 h35
  text "MRAM" at 3237,-3296 h30
  text "D15_2" at 2717,-3300.67 h25
  text "D7" at 1138,-3309 h35
  text "A15_1" at 2988.33,-3309 h25 r270
  text "LBb" at 3237,-3340 h30
  text "LBB" at 2764,-3414 h25
  text "MRAM" at 3238,-3501 h30
  text "D14_2" at 469,-3506.67 h25
  text "UBb" at 3238,-3545 h30
  text "PN: 54_TSSOP_FMC_ADDED_A21" at 1038,-3555 h50
  text "A14_1" at 2830.33,-3619 h25 r270
  text "USBB_1" at 2926.33,-3619 h25 r270
  text "CN11" at 407.4,-3673 h55
  text "CN12" at 2809,-3825 h50
  text "PN: QDS9907_AVL (V0.8)" at 2236,-3954 h50
Bottom Overlay:
  drawing of 1818 lines, arcs and shapes, not listed
  text "1" at 2836,-60 h35
  text "2" at 2963,-70 h35
  text "2" at 551.32,-79 h40
  text "CN7" at 2620,-87 h50
  text "2" at 2670,-113 h40
  text "JP12" at 1380,-156 h45
  text "1" at 358,-163 h40
  text "1" at 2464,-212 h40
  text "VCC" at 2060.16,-289 h40
  text "GND" at 167,-419 h35
  text "CN8" at 871,-438 h60
  text "VOUT" at 2233,-485 h40
  text "+5V0" at 175,-522 h40
  text "GND" at 3324,-524 h35
  text "VIN" at 2146.51,-592 h40
  text "IOREF" at 164,-622 h40
  text "VCC" at 3331,-626 h35
  text "D13" at 3317,-725 h40
  text "RST" at 157,-727 h40
  text "D0" at 3295,-821 h40
  text "SHDN_1" at 1891,-844 h40
  text "D1" at 3278,-926 h40
  text "A6" at 3300,-1022 h40
  text "A7" at 3297,-1122 h40
  text "GND" at 165,-1218 h35
  text "D6" at 3294,-1223 h40
  text "A12" at 151,-1323 h40
  text "D8" at 3298,-1323 h40
  text "A8" at 3295,-1422 h40
  text "A13" at 166,-1424 h40
  text "MRAM" at 159,-1491 h30
  text "MRAM" at 3348,-1506 h30
  text "CEb" at 159,-1535 h30
  text "OEb_ALT" at 3380,-1561 h30
  text "MRAM" at 153,-1602 h30
  text "D10" at 3327,-1626 h40
  text "WEb" at 153,-1646 h30
  text "MRAM" at 156,-1700 h30
  text "A9" at 3293,-1725 h40
  text "OEb" at 156,-1744 h30
  text "A5" at 3301,-1822 h40
  text "A4" at 3302,-1920 h40
  text "OE_DFFb" at 294,-1932 h40
  text "D5" at 3296,-2024 h40
  text "OE_DFFb" at 172,-2092 h30
  text "A18" at 3328,-2122 h40
  text "A20" at 163,-2220 h40
  text "A17" at 3322,-2224 h40
  text "A19" at 165,-2319 h40
  text "D4" at 3299,-2322 h40
  text "MRAM" at 155,-2391 h30
  text "A16" at 3327,-2418 h40
  text "SEb" at 155,-2435 h30
  text "A2" at 167,-2523 h40
  text "D7" at 3294,-2525 h40
  text "BOTTOM SILKSCREEN" at 5467,-2581 h65
  text "D9" at 3296,-2620 h40
  text "A1" at 164,-2623 h40
  text "D2" at 154,-2716 h40
  text "D11" at 3309,-2722 h40
  text "A0" at 160,-2814 h40
  text "D12" at 3325,-2819 h40
  text "GND" at 3228,-2882 h35 r180
  text "D3" at 158,-2920 h40
  text "CN9" at 872,-2984 h60
  text "CN10" at 2689,-3011 h60
  text "A10" at 165,-3018 h40
  text "A3" at 3296,-3023 h40
  text "OE" at 3290,-3094.64 h30
  text "A11" at 160,-3120.34 h40
  text "BUFb" at 3327,-3138 h30
  text "GND" at 168,-3218 h40
  text "D15" at 3323,-3223 h40
  text "MRAM" at 3346,-3296 h30
  text "LBb" at 3346,-3340 h30
  text "A15" at 3328,-3420 h40
  text "MRAM" at 3350,-3502 h30
  text "UBb" at 3349,-3545 h30
  text "D14" at 166,-3575 h40
  text "A14" at 3327,-3620 h40
  text "GND" at 167,-3671 h40
  text "QHO@QDESIGNSERVICES.COM" at 1624.78,-3849.87 h30
  text "TEL: 408-375-8527" at 1626.52,-3901.37 h30
  text "GND" at 2749,-3905 h35
  text "PN: QDS9907_AVL (V0.8)" at 1613.49,-3954.76 h30
Top Paste:
  text "TOP SOLDER PAST" at 5476,-2876.64 h65
Bottom Paste:
  text "BOTTOM SOLDER PAST" at 4070,-2882.64 h65
Top Solder:
  text "TOP SOLDER MASK" at 5472.91,-2724.17 h65
Bottom Solder:
  text "BOTTOM SOLDERMASK" at 4066.91,-2730.17 h65
Assembly:
  circle w10: c223,-264 r25
Dimension:
  pour cut-out: 3145,-3012 3148,-3087 3180,-3065 3170,-3002
  pour cut-out: 414,-862 420,-934 469,-928 479,-883
  lines w10: 225,-3199 225,-3100 ; 640,0 2740,0 2740,-2050 ; 1117.74,-2265.74 1117.74,-1463 2215,-1463 2215,-2309
Outline:
  pour cut-out: 2973,-2041
  lines w8: 2740,0 2740,0
  lines w10: 4002.65,-2770.07 6752.65,-2770.07 ; 4002.65,-2620.07 6752.65,-2620.07 ; 4002.65,-2470.07 6752.65,-2470.07 ; 4002.65,-2320.07 6752.65,-2320.07 ; 4002.65,-2170.07 6752.65,-2170.07 ; 4002.65,-2020.07 6752.65,-2020.07 ; 4002.65,-1870.07 6752.65,-1870.07 ; 4002.65,-1720.07 6752.65,-1720.07 ; 4002.65,-1570.07 6752.65,-1570.07 ; 4002.65,-1294.81 6752.65,-1294.81 ; 4002.65,-1119.81 6752.65,-1119.81 ; 4002.65,-994.81 6752.65,-994.81 ; 4002.65,-869.81 6752.65,-869.81 ; 4002.65,-744.81 6752.65,-744.81 ; 4002.65,-619.81 6752.65,-619.81 ; 4002.65,-494.81 6752.65,-494.81 ; 4002.65,-369.81 6752.65,-369.81 ; 4002.65,-244.81 6752.65,-244.81 ; 4002.65,5.19 6752.65,5.19 ; 4752.84,-1244.81 4752.84,5.19 ; 5377.65,-2920.07 5377.65,-1570.07 ; 6752.65,-2919.89 4002.65,-2919.89 ; 4002.65,-2919.89 4002.65,-3849.9 6752.98,-3849.9 6752.98,-2919.89 4002.65,-2919.89 ; 4002.65,-1244.81 4002.65,-2920.07 6752.65,-2920.07 6752.65,-1244.81 ; 4002.65,-1244.81 6752.65,-1244.81 ; 4002.65,-1244.81 4002.65,1155.19 6752.65,1155.19 6752.65,-1244.81 ; 0,-4000 0,0 3400,0 3400,-4000 0,-4000
  text "Q DESIGN SERVICES, INC." at 4541.17,809.18 h100
  text "1151 RINGWOOD CT, #40" at 4854.71,672.93 h60
  text "SAN JOSE, CA 95131" at 4844.54,567.04 h60
  text "TEL: 408-375-8527" at 4860.54,455.04 h60
  text "FAX: 408-428-9473" at 4864.54,331.04 h60
  text "Title:" at 4374.57,-141.4 h75
  text "54_TSSOP_FMC_ADDED_A21" at 4813.21,-146.2 h65
  text "Customer:" at 4181.08,-331.67 h65
  text "Contact:" at 4265.08,-462.67 h65
  text "CUST P/N#:" at 4103.08,-586.67 h65
  text "JOB#:" at 4387.18,-830.88 h65
  text "QDS9907_AVL (0.8)" at 4880.21,-834.2 h65
  text "ENG./Designer:" at 4080.08,-955.67 h65
  text "Quoc Ho" at 4886.71,-962.88 h65
  text "Scale:" at 4393.08,-1083.67 h65
  text "1 TO 1" at 4886.71,-1087.88 h65
  text "View:" at 4404.57,-1211.4 h65
  text "TOP VIEW" at 4886.71,-1212.88 h65
  text "DATE PLOTTED:" at 4164.38,-1479.13 h65
  text ".Print_Date" at 5491.18,-1485.83 h65
  text "PADMASTER" at 4116.71,-1682.72 h65
  text "DRILLMASTER" at 5491.71,-1682.72 h65
  text "PROPRIETARY NOTICE" at 4510.5,-3069.49 h100
  text "THIS DOCUMENT/FILE AND THE TECHNICAL" at 4175.16,-3198.48 h75
  text "DATA HEREIN DISCLOSED ARE PROPRIETARY" at 4179.06,-3322.86 h75
  text "TO Q DESIGN AND SHALL NOT BE DUPLICATED" at 4156.17,-3450.82 h75
  text "USED, RELEASED, OR DISCLOSED IN" at 4174,-3573.38 h75
  text "WHOLE OR IN PART WITHOUT EXPRESSED" at 4172.63,-3693.88 h75
  text "WRITTEN PERMISSION." at 4179.25,-3814.84 h75
Mechanical:
  lines w5: 740,-1469.69 740,-1450 ; 740,-569.69 740,-550 ; 1638.03,-2070.28 1638.03,-2055.51 ; 2640,-1969.69 2640,-1950 ; 2640,-1109.69 2640,-1090
  lines w10: 1575,-1010 1645,-1010 ; 1645,-1080 1645,-1010 ; 1645,-940 1645,-1010 ; 1715,-1010 1645,-1010 ; 640,-2050 640,0 2740,0 2740,-2050 2230,-2050 2130,-2150 840,-2150 740,-2050 640,-2050 ; 935,0 2460,0 935,0 ; 949.17,-1195.2 1220.83,-1195.2 1220.83,-844.8 949.17,-844.8 949.17,-1195.2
